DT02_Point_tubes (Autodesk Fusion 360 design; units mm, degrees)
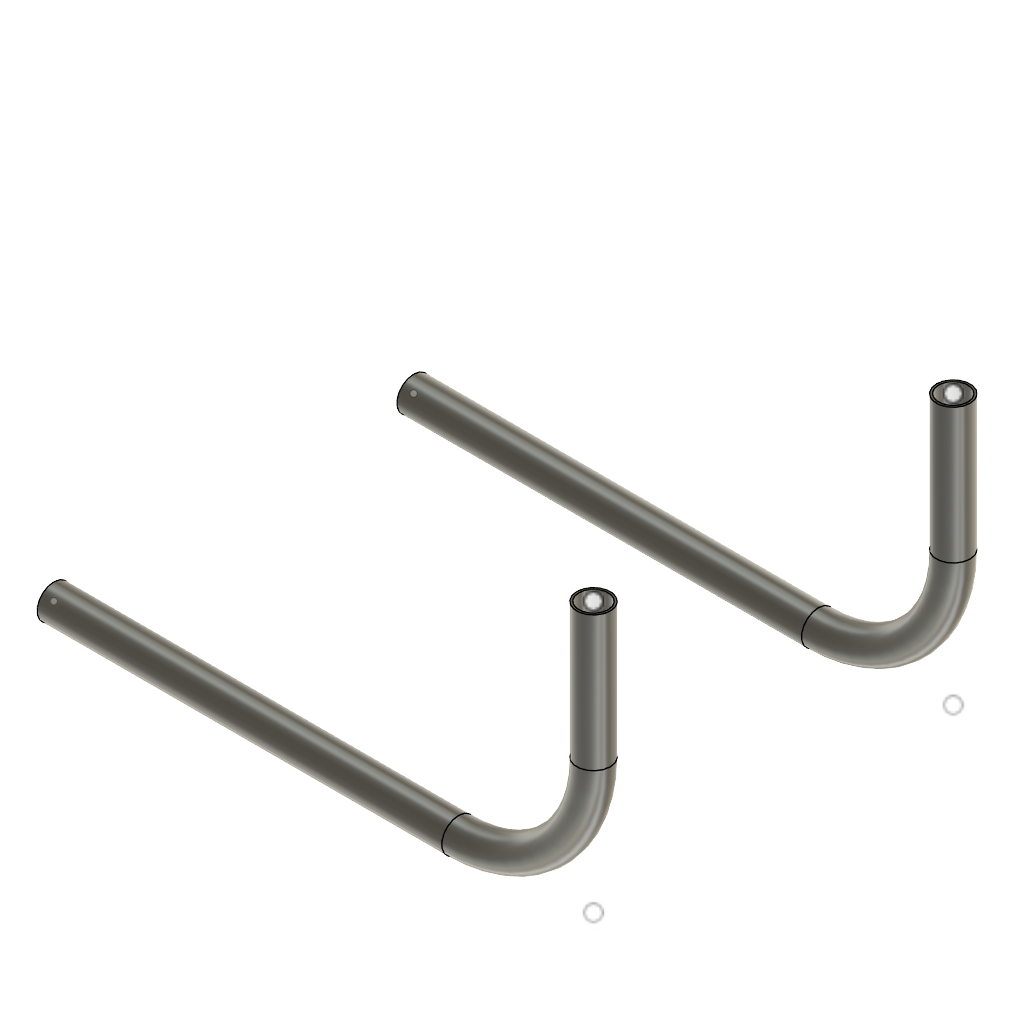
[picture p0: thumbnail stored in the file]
part number: 2026-10-26-12-17-31-515
parameter "OD_DEMO_ONLY_1_5_x_095_R6" = 38.1
parameter "Wall_DEMO_ONLY_1_5_x_095_R6" = 2.413
sketch "Tube points" plane through (0, 0, 0) normal (0, 0, 1) x axis (1, 0, 0)
sketch "TubePoints" plane through (0, 0, 0) normal (0, 0, 1) x axis (1, 0, 0)
work_plane "WorkPlane1" ExtraOffset 0
sketch "Sketch3" plane through (0, 203.2, 0) normal (1, 0, 0) x axis (0, 0, 1)
  circle C1 centre (0, 0) radius 19.05
  circle C2 centre (0, 0) radius 16.637
  dimension "d5" diameter C1 = 38.1 (= "OD_DEMO_ONLY_1_5_x_095_R6")
  dimension "d6" diameter C2 = 33.274 (= "OD_DEMO_ONLY_1_5_x_095_R6 - 2 * Wall_DEMO_ONLY_1_5_x_095_R6")
sweep "Sweep1" sketch "Sketch3" TwistAngle 0 TaperAngle 0 bodies "P1 Mirrored point tube"
sketch "TubePoints-m" plane through (0, 0, 0) normal (0, 0, 1) x axis (1, 0, 0)
work_plane "WorkPlane2" ExtraOffset 0
sketch "Sketch5" plane through (0, -203.2, 0) normal (1, 0, 0) x axis (0, 0, 1)
  circle C1 centre (0, 0) radius 19.05
  circle C2 centre (0, 0) radius 16.637
  dimension "d15" diameter C1 = 38.1 (= "OD_DEMO_ONLY_1_5_x_095_R6")
  dimension "d16" diameter C2 = 33.274 (= "OD_DEMO_ONLY_1_5_x_095_R6 - 2 * Wall_DEMO_ONLY_1_5_x_095_R6")
sweep "Sweep2" sketch "Sketch5" TwistAngle 0 TaperAngle 0 bodies "P2 Mirrored point tube"
sketch "3D practice frame - tube paths" plane through (0, 0, 0) normal (0, 0, 1) x axis (1, 0, 0)
  line L1 (457.2, 0) -> (0, 0)
  line L2 (609.6, 304.8) -> (609.6, 152.4)
  line L3 (609.6, 457.2) -> (609.6, 457.2)
  arc A1 centre (457.2, 152.4) radius 152.4 clockwise from (609.6, 152.4) to (457.2, 0)
  arc A2 centre (609.6, 304.8) radius 152.4 between (609.6, 304.8) and (609.6, 457.2)
  tangent L1 A1
  tangent L2 A1
  tangent L2 A2
  tangent L3 A2
work_plane "WorkPlane3" ExtraOffset 0
sketch "Sketch8" plane through (0, 0, 0) normal (1, 0, 0) x axis (0, 0, 1)
  circle C1 centre (0, 0) radius 19.05
  circle C2 centre (0, 0) radius 16.637
  dimension "d25" diameter C1 = 38.1 (= "OD_DEMO_ONLY_1_5_x_095_R6")
  dimension "d26" diameter C2 = 33.274 (= "OD_DEMO_ONLY_1_5_x_095_R6 - 2 * Wall_DEMO_ONLY_1_5_x_095_R6")
named bodies: "P1 Mirrored point tube", "P2 Mirrored point tube"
